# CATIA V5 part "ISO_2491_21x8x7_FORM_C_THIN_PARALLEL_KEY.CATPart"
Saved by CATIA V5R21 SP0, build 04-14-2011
Part number: ISO 2491 KEY 20x5x3 THIN PARALLEL FORM C
Publications: "Mating Face", "Axis"
Bounding box of the stored display mesh (mm): x 0 to 20.804, y -4 to 4, z 0 to 7
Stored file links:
  C:\Users\MIRCEA\Desktop\MOM\Mogan\model\ISO_2491_21x8x7_FORM_C_THIN_PARALLEL_KEY.CATPart
  C:\Program Files (x86)\Dassault Systemes\B21\intel_a\startup\components\MechanicalStandardParts\ISO_Standards\Design_Tables\ISO_2491_THIN_PARALLEL_KEY_FORM_C.txt
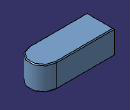
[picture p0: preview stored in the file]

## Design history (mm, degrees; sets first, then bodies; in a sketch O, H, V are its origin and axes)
Parameters
  l_length = 21 mm
  b_width = 8 mm
  h_thickness = 7 mm
  s_chamfer_min = 0.25 mm
  `Part Name` = "ISO 2491 KEY 14x6x4 THIN PARALLEL FORM C"
  `Part Number` = "ISO_2491_14x6x4_THIN_PARALLEL_KEY_FORM_C"
  PartName = "ISO_2491_20x5x3_FORM_C_THIN_PARALLEL_KEY"
  PartNumber = "ISO 2491 KEY 20x5x3 THIN PARALLEL FORM C"
Body1 "PartBody" (main body)
  Sketch1 on xy-plane, origin (0, 0, 0), H (1, 0, 0), V (0, 1, 0)
    line L1 (0, -4) -> (0, 4)
    line L2 (0, 4) -> (17, 4)
    arc A1 centre (17, 0) radius 4 from (17, 4) to (17, -4) cw
    point P5 (17, 0)
    line L3 (17, -4) -> (0, -4)
    radius A1 = 4 {= b_width *.5}
    distance L2 H = 4 {= b_width /2}
    distance L1 P5 = 17 {= l_length -Sketch1.radius(A1)}
    vertical: L1 V
    tangency: A1 L2, L3 A1
    coincidence: L1 V
    horizontal: L3 H
  Pad1: profile Sketch1, direction (0, 0, 1), length 7 {= h_thickness}
  Chamfer1: length 0.25 {= s_chamfer_min}, angle 45, on edge [face of Pad1 | face of Pad1] (x2); face of Pad1
  Chamfer2: length 0.25 {= s_chamfer_min}, angle 45, on edge [face of Pad1 | face of Pad1] (x3)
